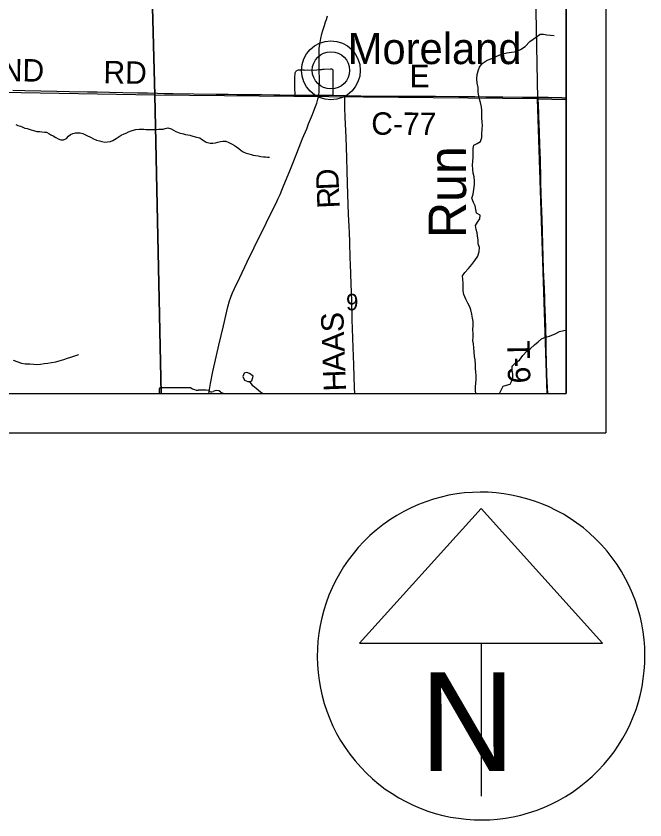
# Model space of a CAD drawing. Extents: x 0 to 34, y 0 to 22.
# Drawn here: x 7.507 to 9.099, y 13.02 to 15.055 of the extents above; entities that cross this region are included whole.
import ezdxf

# ---------------------------------------------------------------- set-up
doc = ezdxf.new("R2010")
doc.units = 0
for name, color, linetype in [('Default', 7, 'Continuous'), ('GM_X_Corporation_Text', 7, 'Continuous'), ('GM_X_County_Road', 7, 'Continuous'), ('GM_X_County_Road_Text', 7, 'Continuous'), ('GM_X_Minor_Lake', 7, 'Continuous'), ('GM_X_Minor_River', 7, 'Continuous'), ('GM_X_Minor_River_Text', 7, 'Continuous'), ('GM_X_Section', 7, 'Continuous'), ('GM_X_Section_Text', 7, 'Continuous'), ('GM_X_State_Route', 7, 'Continuous'), ('GM_X_Township_Road', 7, 'Continuous'), ('GM_X_Township_Road_Text', 7, 'Continuous'), ('GM_X_Unincorporated', 7, 'Continuous'), ('GM_X_Unincorporated_Location', 7, 'Continuous'), ('GM_X_Unincorporated_Text', 7, 'Continuous'), ('SH_Data', 7, 'Continuous')]:
    doc.layers.add(name, color=color, linetype=linetype)

msp = doc.modelspace()

# ---------------------------------------------------------------- linework, layer by layer
at = {"layer": 'Default'}
for points in [[(8.9, 14.8441), (8.9, 15.8688), (8.808, 15.8683), (8.8276, 14.8459)], [(6.8542, 14.1), (7.8747, 14.1), (7.8581, 14.855), (6.8411, 14.8726), (6.8396, 14.3761)], [(7.8747, 14.1), (8.8519, 14.1), (8.8276, 14.8459), (7.8581, 14.855)], [(8.8519, 14.1), (8.9, 14.1), (8.9, 14.8441), (8.8276, 14.8459)]]:
    msp.add_lwpolyline(points, close=True, dxfattribs=at)
at = {"layer": 'GM_X_Corporation_Text'}
msp.add_line((7.9496, 14.1145), (7.8723, 14.1145), dxfattribs=at)
msp.add_lwpolyline([(7.8698, 14.111), (7.8698, 14.1), (8.0343, 14.1)], dxfattribs=at)
for centre, radius, start, end in [((7.8728, 14.1115), 0.00305, 98.978, 188.5967), ((7.968, 14.1377), 0.0296, 231.6404, 271.1117), ((7.9778, 14.0021), 0.1064, 80.4867, 94.9883), ((8.002, 14.1125), 0.00855, 219.7921, 297.1024), ((8.0145, 14.0894), 0.0178, 54.4667, 119.1411), ((8.0374, 14.1211), 0.0214, 233.8562, 261.5373)]:
    msp.add_arc(centre, radius, start, end, dxfattribs=at)
at = {"layer": 'GM_X_County_Road'}
for points in [[(7.4986, 14.8673), (7.5296, 14.8666), (7.5699, 14.8661), (7.6103, 14.865), (7.6413, 14.8643), (7.6878, 14.8635), (7.7126, 14.863), (7.7436, 14.8623), (7.7778, 14.8615), (7.8149, 14.861), (7.8397, 14.8606), (7.8656, 14.8598), (7.8832, 14.8596), (7.9049, 14.8591), (7.9576, 14.8584), (8.0135, 14.8579), (8.0321, 14.8576), (8.0445, 14.8574), (8.0662, 14.857), (8.1284, 14.8563), (8.1594, 14.8558), (8.1748, 14.8556), (8.2058, 14.8552), (8.2137, 14.8551)], [(8.2137, 14.8551), (8.2366, 14.8549), (8.2549, 14.8549), (8.2689, 14.855), (8.2737, 14.855)], [(8.2737, 14.855), (8.2813, 14.8549), (8.3003, 14.8548), (8.309, 14.8547)], [(8.309, 14.8547), (8.3363, 14.8545), (8.3391, 14.8544)], [(8.3391, 14.8544), (8.3611, 14.8537), (8.3798, 14.8532), (8.4046, 14.8528), (8.4636, 14.8525), (8.5474, 14.8522), (8.5692, 14.8521), (8.6281, 14.8516), (8.6684, 14.8512), (8.6964, 14.8509), (8.7181, 14.8507), (8.7398, 14.8506), (8.7895, 14.8503), (8.8292, 14.85)], [(8.8292, 14.85), (8.833, 14.85), (8.8547, 14.8496), (8.8887, 14.8487), (8.9, 14.8483)]]:
    msp.add_lwpolyline(points, dxfattribs=at)
at = {"layer": 'GM_X_Minor_Lake'}
for points in [[(8.1074, 14.1441), (8.0983, 14.1505), (8.0911, 14.1531), (8.0846, 14.1512), (8.0813, 14.1432), (8.0855, 14.1334), (8.0942, 14.1304), (8.0995, 14.13), (8.1037, 14.1319)], [(8.1037, 14.1319), (8.1074, 14.1441)]]:
    msp.add_lwpolyline(points, dxfattribs=at)
at = {"layer": 'GM_X_Minor_River'}
for points in [[(8.6647, 14.6574), (8.6635, 14.6669), (8.6631, 14.6783), (8.6635, 14.687), (8.6642, 14.698), (8.6646, 14.7109), (8.6642, 14.7197), (8.6661, 14.728), (8.6744, 14.733), (8.6831, 14.7375), (8.6861, 14.7478), (8.6861, 14.7565), (8.6869, 14.7694), (8.688, 14.7782), (8.6876, 14.7865), (8.6868, 14.7979), (8.6868, 14.8162), (8.6856, 14.8257), (8.683, 14.8363), (8.6807, 14.8447), (8.6788, 14.853), (8.6769, 14.8626), (8.6772, 14.874), (8.6749, 14.8857), (8.6738, 14.896), (8.6742, 14.9074), (8.6772, 14.9165), (8.6802, 14.9256), (8.6874, 14.9355), (8.7002, 14.9435), (8.7116, 14.9476), (8.7241, 14.9537), (8.7362, 14.959), (8.7498, 14.9624), (8.7619, 14.9635), (8.7752, 14.9658), (8.7839, 14.9703), (8.7964, 14.9779), (8.8077, 14.9908), (8.8244, 15.0029), (8.8342, 15.009), (8.8429, 15.0097), (8.8512, 15.0074), (8.8599, 15.0067), (8.8698, 15.0059)], [(7.5062, 14.7805), (7.5115, 14.7782), (7.5183, 14.7767)], [(7.5183, 14.7767), (7.524, 14.774), (7.5297, 14.7717), (7.5353, 14.7702), (7.5452, 14.7675), (7.5513, 14.7656), (7.56, 14.7633), (7.5664, 14.7629), (7.5725, 14.7621), (7.5789, 14.7617), (7.5838, 14.7614), (7.5899, 14.7579), (7.5948, 14.7549), (7.6013, 14.7518), (7.6077, 14.7476), (7.6134, 14.7442), (7.6202, 14.7419), (7.6274, 14.7423), (7.6346, 14.7457), (7.6399, 14.751), (7.6452, 14.7552), (7.6508, 14.7578), (7.6577, 14.7593), (7.6633, 14.7597), (7.6694, 14.7597), (7.6762, 14.7578), (7.6849, 14.7536), (7.6971, 14.7475), (7.7031, 14.7441), (7.7111, 14.7414), (7.7187, 14.7395), (7.7243, 14.7379), (7.7315, 14.7364), (7.7387, 14.7368), (7.7463, 14.7375), (7.7524, 14.7402), (7.7603, 14.7451), (7.7679, 14.7504), (7.7735, 14.7538), (7.7811, 14.7572), (7.786, 14.7591), (7.7921, 14.7622), (7.8012, 14.7652), (7.8102, 14.7678), (7.819, 14.769), (7.8243, 14.7689), (7.8303, 14.7686), (7.836, 14.7682), (7.8409, 14.7678), (7.8504, 14.7681), (7.8617, 14.7681), (7.8682, 14.7685), (7.8731, 14.7685), (7.8799, 14.7692), (7.8848, 14.7707), (7.8917, 14.7719), (7.8996, 14.7696), (7.9061, 14.7661), (7.9114, 14.7631), (7.9197, 14.76), (7.9311, 14.757), (7.936, 14.7555), (7.9424, 14.7547), (7.9473, 14.7535), (7.9549, 14.7516), (7.964, 14.749), (7.972, 14.7467), (7.9769, 14.744), (7.9833, 14.7394), (7.9886, 14.7364), (7.9985, 14.7337), (8.0053, 14.7333), (8.0117, 14.7341), (8.0182, 14.7359), (8.025, 14.7378), (8.031, 14.7386), (8.0386, 14.7382), (8.0462, 14.7351), (8.0545, 14.7309), (8.0598, 14.7279), (8.0655, 14.7241), (8.0712, 14.7199), (8.0769, 14.7153), (8.0822, 14.7119), (8.0898, 14.7081), (8.0966, 14.7062), (8.1023, 14.705), (8.1076, 14.7035), (8.1133, 14.7023), (8.1197, 14.7012), (8.1269, 14.6997), (8.1333, 14.6989), (8.1383, 14.6985), (8.1436, 14.6977), (8.1489, 14.6977)], [(8.671, 14.1), (8.67, 14.1078), (8.67, 14.1166), (8.6711, 14.1261), (8.6718, 14.1352), (8.6722, 14.1458), (8.6714, 14.1542), (8.6707, 14.1633), (8.6703, 14.1728), (8.6691, 14.185), (8.668, 14.1937), (8.6668, 14.2047), (8.6664, 14.2158), (8.6653, 14.2253), (8.6638, 14.234), (8.6645, 14.2428), (8.6641, 14.2523), (8.6637, 14.2614), (8.6645, 14.272), (8.6641, 14.2823), (8.6629, 14.2906), (8.661, 14.3009), (8.6583, 14.3112), (8.6557, 14.3195), (8.6511, 14.3283), (8.6458, 14.3389), (8.6409, 14.3503), (8.639, 14.3598), (8.6389, 14.3788), (8.6385, 14.3891), (8.6378, 14.3975), (8.6431, 14.4058), (8.6525, 14.4161), (8.6608, 14.4267), (8.6684, 14.4362), (8.676, 14.4472), (8.6793, 14.459), (8.6801, 14.4696), (8.6774, 14.4783), (8.677, 14.4878), (8.6755, 14.4985), (8.6744, 14.5069), (8.6724, 14.5152), (8.6702, 14.5251), (8.6751, 14.5335), (8.6815, 14.5418), (8.6819, 14.5513), (8.6728, 14.5559), (8.6712, 14.5658), (8.6697, 14.5749), (8.6652, 14.5836), (8.661, 14.5943), (8.6644, 14.6042), (8.6659, 14.6163), (8.6681, 14.6285), (8.6681, 14.6372), (8.667, 14.6482), (8.6647, 14.6574)], [(8.7304, 14.1), (8.7317, 14.1013), (8.7359, 14.1096), (8.74, 14.1184), (8.7487, 14.121), (8.7578, 14.1237), (8.7624, 14.132), (8.765, 14.1404), (8.765, 14.1491), (8.7631, 14.1582), (8.7631, 14.1689), (8.7721, 14.1784), (8.7816, 14.184), (8.7899, 14.1962), (8.8005, 14.2068), (8.8099, 14.214), (8.8198, 14.2227), (8.8289, 14.2307), (8.8372, 14.2379), (8.8474, 14.2421), (8.858, 14.2451), (8.8724, 14.2512), (8.8834, 14.2565), (8.8936, 14.2591), (8.9, 14.2599)], [(7.4995, 14.1839), (7.5207, 14.1766), (7.5301, 14.1747), (7.5419, 14.1747), (7.551, 14.1743), (7.5601, 14.1735), (7.5691, 14.1742), (7.5782, 14.1754), (7.5873, 14.1769), (7.5968, 14.1784), (7.6078, 14.1803), (7.6161, 14.1829), (7.6278, 14.1859), (7.6377, 14.1889), (7.646, 14.1916), (7.6558, 14.1954), (7.6657, 14.1984)], [(8.1314, 14.1), (8.1259, 14.1034), (8.1149, 14.1125), (8.1062, 14.119), (8.0991, 14.13)]]:
    msp.add_lwpolyline(points, dxfattribs=at)
at = {"layer": 'GM_X_Section'}
for points in [[(6.8272, 15.8734), (7.8036, 15.873), (7.8312, 15.8725), (7.8581, 14.855), (6.8411, 14.8726)], [(7.8312, 15.8725), (8.808, 15.8683), (8.8276, 14.8459), (7.8581, 14.855)]]:
    msp.add_lwpolyline(points, close=True, dxfattribs=at)
at = {"layer": 'GM_X_State_Route'}
msp.add_lwpolyline([(7.8042, 16.2626), (7.8024, 15.8725), (6.7968, 15.8774), (5.6416, 15.8841), (5.6436, 15.468), (5.6455, 14.1), (8.9, 14.1), (8.9, 18.8876), (8.7984, 18.8872), (8.8033, 17.8763), (8.296, 17.8766), (7.7904, 17.865), (7.8038, 16.9797), (7.9972, 16.9797), (7.9972, 16.2626)], close=True, dxfattribs=at)
for points in [[(8.1754, 14.6033), (8.1801, 14.6143), (8.1854, 14.6275), (8.1999, 14.6636), (8.2101, 14.6891), (8.2163, 14.7038), (8.2301, 14.7386), (8.2326, 14.7451), (8.2429, 14.7701), (8.2476, 14.7824), (8.2573, 14.8059), (8.2638, 14.8223), (8.2683, 14.8344), (8.2694, 14.8377), (8.2706, 14.8417), (8.2713, 14.8446), (8.273, 14.8508), (8.2737, 14.855), (8.2745, 14.8635), (8.2749, 14.8728), (8.2749, 14.879), (8.2751, 14.8851), (8.2754, 14.8882), (8.2751, 14.9003), (8.275, 14.9034), (8.2749, 14.9096), (8.2749, 14.9131), (8.2748, 14.9198), (8.2746, 14.9344), (8.2746, 14.9405), (8.2746, 14.946), (8.2746, 14.9491), (8.2745, 14.9647), (8.2748, 14.9739), (8.276, 14.983), (8.2789, 14.9981), (8.2817, 15.0101), (8.2842, 15.0189), (8.288, 15.0311), (8.2909, 15.0405), (8.2927, 15.0462), (8.2956, 15.0554)], [(8.05, 14.3411), (8.0515, 14.346), (8.0549, 14.3546), (8.0599, 14.366), (8.0735, 14.3938), (8.0926, 14.4329), (8.1102, 14.4693), (8.1403, 14.5306), (8.1579, 14.567), (8.1661, 14.5837), (8.1701, 14.5917), (8.1734, 14.5988), (8.1754, 14.6033)], [(7.9948, 14.1), (7.9996, 14.1255), (8.0056, 14.1559), (8.0101, 14.1772), (8.0208, 14.2225), (8.0322, 14.2709), (8.0436, 14.3193), (8.0477, 14.3342), (8.05, 14.3411)]]:
    msp.add_lwpolyline(points, dxfattribs=at)
at = {"layer": 'GM_X_Township_Road'}
for points in [[(8.2137, 14.8551), (8.2136, 14.8578), (8.2134, 14.8627), (8.2133, 14.8679), (8.2132, 14.8767), (8.2132, 14.8796), (8.2132, 14.8842), (8.2131, 14.8884), (8.2129, 14.8941), (8.2131, 14.8986), (8.2132, 14.9022), (8.2134, 14.907), (8.2141, 14.9118), (8.2151, 14.9147), (8.2159, 14.9159), (8.2169, 14.9171), (8.218, 14.9178), (8.2195, 14.9184), (8.222, 14.9188), (8.2256, 14.919), (8.2296, 14.9189), (8.2354, 14.9187), (8.2385, 14.9186), (8.2447, 14.9187), (8.2601, 14.9186), (8.2687, 14.9191), (8.2748, 14.9198)], [(8.2748, 14.9198), (8.2786, 14.92), (8.2813, 14.9203), (8.284, 14.9205), (8.2875, 14.9208), (8.3032, 14.9217), (8.3047, 14.9218), (8.3059, 14.9215), (8.3073, 14.9209), (8.3081, 14.9201), (8.3089, 14.9188), (8.3092, 14.9171), (8.3091, 14.9135), (8.3091, 14.8961), (8.309, 14.8747), (8.309, 14.8596), (8.309, 14.8547)], [(8.3648, 14.1), (8.3644, 14.1138), (8.3626, 14.1727), (8.3609, 14.2161), (8.3584, 14.2875), (8.3569, 14.334), (8.3554, 14.3772), (8.3538, 14.4268), (8.3533, 14.4423), (8.3518, 14.4826), (8.351, 14.5074), (8.3504, 14.5229), (8.3491, 14.5539), (8.3475, 14.6035), (8.3454, 14.6624), (8.3442, 14.6965), (8.3427, 14.7487), (8.3406, 14.7987), (8.3399, 14.8238), (8.3395, 14.8405), (8.3391, 14.8544)], [(8.8538, 14.1), (8.8532, 14.1037), (8.8526, 14.1099), (8.8523, 14.1164), (8.8518, 14.1277), (8.8514, 14.134), (8.8512, 14.1371), (8.8506, 14.1536), (8.85, 14.1712), (8.8498, 14.1863), (8.8493, 14.2046), (8.8492, 14.217), (8.849, 14.2293), (8.849, 14.2355), (8.8489, 14.2417), (8.8489, 14.2448), (8.8489, 14.2479), (8.8488, 14.251), (8.8486, 14.2633), (8.8476, 14.2943), (8.847, 14.3097), (8.8462, 14.3311), (8.8461, 14.3343), (8.8458, 14.3373), (8.8457, 14.3403), (8.8447, 14.3651), (8.8434, 14.3961), (8.8427, 14.4147), (8.8419, 14.4458), (8.841, 14.4769), (8.8389, 14.5421), (8.8382, 14.5607), (8.837, 14.6041), (8.8359, 14.6352), (8.8358, 14.6536), (8.835, 14.6814), (8.8346, 14.6939), (8.8342, 14.7094), (8.8336, 14.7311), (8.8327, 14.759), (8.8317, 14.7838), (8.831, 14.7993), (8.8305, 14.8117), (8.8299, 14.8272), (8.8293, 14.8482), (8.8292, 14.85)]]:
    msp.add_lwpolyline(points, dxfattribs=at)
at = {"layer": 'GM_X_Unincorporated'}
for radius in [0.0744, 0.0472]:
    msp.add_circle((8.3043, 14.9178), radius, dxfattribs=at)
at = {"layer": 'GM_X_Unincorporated_Location'}
msp.add_line((8.3043, 14.9178), (8.3043, 14.9178), dxfattribs=at)
at = {"layer": 'SH_Data'}
for p, q in [((9, 21), (9, 14)), ((8.9, 20.9), (8.9, 14.1)), ((2.1, 14.1), (8.9, 14.1)), ((2, 14), (9, 14)), ((8.6845, 13.809), (8.3769, 13.4678)), ((8.9921, 13.4678), (8.6845, 13.809)), ((8.3769, 13.4678), (8.9921, 13.4678)), ((8.6845, 13.4678), (8.6845, 13.081)), ((8.6845, 13.4353), (8.6845, 13.4353)), ((8.6845, 13.4353), (8.6845, 13.4353))]:
    msp.add_line(p, q, dxfattribs=at)
msp.add_arc((8.6845, 13.4353), 0.4148, 129.7798, 129.7633, dxfattribs=at)

# ---------------------------------------------------------------- texts
at = {"layer": 'GM_X_County_Road_Text'}
for s, height, rotation, p in [('MORELAND', 0.05682, 359.0526, (7.1473, 14.896)), ('RD', 0.05682, 359.0132, (7.728, 14.8851)), ('E', 0.0568, 0, (8.5035, 14.8751)), ('C-77', 0.05682, 359.6563, (8.4063, 14.7549))]:
    msp.add_text(s, height=height, rotation=rotation, dxfattribs=at).set_placement(p)
at = {"layer": 'GM_X_Minor_River_Text'}
msp.add_text('Run', height=0.09472, rotation=89.9058, dxfattribs=at).set_placement((8.6462, 14.4933))
at = {"layer": 'GM_X_Section_Text'}
msp.add_text('9', height=0.0419, rotation=0, dxfattribs=at).set_placement((8.3426, 14.3103))
at = {"layer": 'GM_X_Township_Road_Text'}
for s, rotation, p in [('D', 92.3758, (8.3249, 14.6158)), ('R', 92.5769, (8.327, 14.5693)), ('S', 91.7012, (8.3373, 14.2559)), ('A', 92.0987, (8.3391, 14.2061)), ('T', 270.9943, (8.7507, 14.2334)), ('A', 92.1106, (8.3409, 14.1561)), ('-', 271.0484, (8.7514, 14.1908)), ('9', 271.3507, (8.7518, 14.1671)), ('H', 92.1096, (8.3428, 14.1061))]:
    msp.add_text(s, height=0.0568, rotation=rotation, dxfattribs=at).set_placement(p)
at = {"layer": 'GM_X_Unincorporated_Text'}
msp.add_text('Moreland', height=0.07898, rotation=0, dxfattribs=at).set_placement((8.3468, 14.9336))
at = {"layer": 'SH_Data'}
msp.add_text('N', height=0.25, dxfattribs=at).set_placement((8.5292, 13.1439))

doc.saveas('drawing.dxf')
